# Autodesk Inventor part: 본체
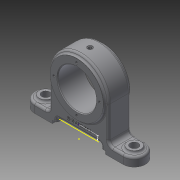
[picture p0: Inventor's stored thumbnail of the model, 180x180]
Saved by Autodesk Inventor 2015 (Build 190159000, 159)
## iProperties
Created: 2019-05
Part Number: 본체
Material: 일반
Document SubType Name: Modeling
Designer: 102101
Density: 1 g/cm^3
Appearance: 기본값
Author: 102101
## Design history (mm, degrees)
sketch "스케치1"
  geometry: L1 (75, -15)-(-75, -15); L2 (-75, -15)-(-75, 15); L3 (-75, 15)-(75, 15); L4 (75, 15)-(75, -15); L5 (75, -15)-(-75, 15); L6 (-75, -15)-(75, 15); 1 further point
  constraints: 12 end point, 2 midpoint, 2 parallel, 1 horizontal, 1 perpendicular
  dimensions: "d0" = 150 distance of L2.end L3.end; "d1" = 30 distance of L3.end L1.start
extrude "돌출1" new body sketch "스케치1" distance "d2" = 12; taper "d3" = 0 deg
fillet "모깎기1" dims "d4" = 15
fillet "모깎기2" dims "d5" = 15
sketch "스케치2"
  geometry: C1 r 9 at (-60, 0); C2 r 9 at (60, 0); 1 further point
  constraints: 2 centre point, 2 horizontal alignment
  dimensions: "d6" = 18 diameter of C1; "d7" = 18 diameter of C2; "d8" = 120 distance of C2.centre C1.centre; "d9" = 60 distance of point (0, 0) C1.centre
extrude "돌출2" join sketch "스케치2" distance "d10" = 3; taper "d11" = 0 deg
sketch "스케치3"
  geometry: L1 (0, 0)-(-120, 0) reference; L2 (-96, 0)-(-24, 0); L3 (-24, 0)-(-24, 4); L4 (-24, 4)-(-96, 4); L5 (-96, 4)-(-96, 0); 2 further points
  constraints: 8 end point, 2 midpoint, 2 parallel, 1 horizontal, 1 perpendicular, 1 point on line
  dimensions: "d12" = 72 distance of L3.end L4.end; "d13" = 4 distance between parallel lines of L4 L1
extrude "돌출3" cut sketch "스케치3" stored distance "d14" = 3; taper "d15" = 0 deg
sketch "스케치4"
  geometry: L1 (-96, 4)-(-24, 4) reference; L2 (-90, 4)-(-30, 4); L3 (-30, 4)-(-30, 10); L4 (-30, 10)-(-90, 10); L5 (-90, 10)-(-90, 4); 2 further points
  constraints: 8 end point, 2 midpoint, 2 parallel, 1 horizontal, 1 perpendicular, 1 point on line
  dimensions: "d16" = 60 distance between parallel lines of L3 L5; "d17" = 6 distance between parallel lines of L1 L4
extrude "돌출4" cut sketch "스케치4" stored distance "d18" = 3; taper "d19" = 0 deg
sketch "스케치5"
  geometry: L1 (40, -15)-(-40, -15); L2 (-40, -15)-(-40, 15); L3 (-40, 15)-(40, 15); L4 (40, 15)-(40, -15); L5 (40, -15)-(-40, 15); L6 (-40, -15)-(40, 15); 1 further point
  constraints: 12 end point, 2 midpoint, 2 parallel, 1 horizontal, 1 perpendicular
  dimensions: "d20" = 80 distance of L2.end L3.end; "d21" = 30 distance between parallel lines of L1 L3
extrude "돌출5" join sketch "스케치5" distance "d22" = 48; taper "d23" = 0 deg
sketch "스케치6"
  geometry: L1 (40, 60)-(-40, 60) reference; L2 (-36, 4)-(-36, 0) reference; L3 (-36, 0)-(-75, 0) reference; L4 (-75, 0)-(-75, 12) reference; L5 (-75, 12)-(-69, 12) reference; L6 (-69, 12)-(-69, 15) reference; L7 (-69, 15)-(-51, 15) reference; L8 (-51, 15)-(-51, 12) reference; L9 (-51, 12)-(-40, 12) reference; L10 (-40, 12)-(-40, 60) reference; L11 (-40, 60)-(40, 60) reference; L12 (40, 60)-(40, 12) reference; L13 (40, 12)-(51, 12) reference; L14 (51, 12)-(51, 15) reference; L15 (51, 15)-(69, 15) reference; L16 (69, 15)-(69, 12) reference; L17 (69, 12)-(75, 12) reference; L18 (75, 12)-(75, 0) reference; L19 (75, 0)-(36, 0) reference; L20 (36, 0)-(36, 4) reference; L21 (36, 4)-(30, 4) reference; L22 (30, 4)-(30, 10) reference; L23 (30, 10)-(-30, 10) reference; L24 (-30, 10)-(-30, 4) reference; L25 (-30, 4)-(-36, 4) reference; C1 r 40 at (0, 60); 3 further points
  constraints: 3 vertical alignment, 2 midpoint, 1 centre point
  dimensions: "d24" = 80 diameter of C1; "d25" = 60 distance of point (0, 0) C1.centre
extrude "돌출6" join sketch "스케치6" stored distance "d26" = 30; taper "d27" = 0 deg
sketch "스케치7"
  geometry: L1 (-36, 4)-(-36, 0) reference; L2 (-36, 0)-(-75, 0) reference; L3 (-75, 0)-(-75, 12) reference; L4 (-75, 12)-(-69, 12) reference; L5 (-69, 12)-(-69, 15) reference; L6 (-69, 15)-(-51, 15) reference; L7 (-51, 15)-(-51, 12) reference; L8 (-51, 12)-(-40, 12) reference; L9 (-40, 12)-(-40, 60) reference; L10 (40, 60)-(40, 12) reference; L11 (40, 12)-(51, 12) reference; L12 (51, 12)-(51, 15) reference; L13 (51, 15)-(69, 15) reference; L14 (69, 15)-(69, 12) reference; L15 (69, 12)-(75, 12) reference; L16 (75, 12)-(75, 0) reference; L17 (75, 0)-(36, 0) reference; L18 (36, 0)-(36, 4) reference; L19 (36, 4)-(30, 4) reference; L20 (30, 4)-(30, 10) reference; L21 (30, 10)-(-30, 10) reference; L22 (-30, 10)-(-30, 4) reference; L23 (-30, 4)-(-36, 4) reference; C1 r 36 at (0, 60); A1 r 40 centre (0, 60) between (40, 60) and (-40, 60) reference; 1 further point
  constraints: 1 centre point, 1 coincident
  dimensions: "d28" = 72 diameter of C1
extrude "돌출7" join sketch "스케치7" stored distance "d29" = 36; taper "d30" = 0 deg
sketch "스케치8"
  geometry: C1 r 26 at (0, 0); 1 further point
  constraints: 1 centre point, 1 vertical alignment
  dimensions: "d31" = 52 diameter of C1; "d32" = 60 distance of point (0, -60) C1.centre
extrude "돌출8" cut sketch "스케치8" stored distance "d33" = 10; taper "d34" = 0 deg
sketch "스케치9"
  geometry: 2 further points
  dimensions: "d35" = 91 distance of point (0, -60) point (0, 31)
hole "구멍1" sketch "스케치9" at (0, 31) diameter "d36" = 3.242; stored, may be unused: countersink angle "d40" = 90 deg, drill point angle "d42" = 118 deg; dims "d37" = 6, "d38" = 4, "d39" = 2, "d41" = 8
sketch "스케치10"
  geometry: A1 r 15 centre (0, 0) between (0, 15) and (0, -15) reference; 1 further point
hole "구멍2" sketch "스케치10" at (0, 0) diameter "d46" = 11; stored, may be unused: countersink angle "d50" = 90 deg, drill point angle "d52" = 118 deg; dims "d47" = 6, "d48" = 4, "d49" = 2, "d51" = 8
node "작업 평면1"
sketch "스케치11"
  geometry: 1 further point
hole "구멍3" sketch "스케치11" at (0, 0) diameter "d54" = 4.917; stored, may be unused: countersink angle "d58" = 90 deg, drill point angle "d60" = 118 deg; dims "d55" = 8, "d56" = 7, "d57" = 1, "d59" = 10
sketch "스케치12"
  geometry: 1 further point
hole "구멍4" sketch "스케치12" at (0, 0) diameter "d61" = 2; stored, may be unused: countersink angle "d65" = 90 deg, drill point angle "d67" = 118 deg; dims "d62" = 8, "d63" = 7, "d64" = 1, "d66" = 30
fillet "모깎기3" dims "d68" = 3
chamfer "모따기1" distance "d69" = 1; stored, may be unused: second distance "d70" = 2, angle "d71" = 45 deg
sketch "스케치13"
  geometry: C1 r 1.5 at (0, 26); 2 further points
  constraints: 2 vertical alignment, 1 centre point, 1 other
  dimensions: "d72" = 3 diameter of C1
extrude "돌출9" cut sketch "스케치13" stored distance "d73" = 10; taper "d74" = 0 deg
fillet "모깎기4" dims "d75" = 6
fillet "모깎기5" dims "d76" = 3
fillet "모깎기6" dims "d77" = 3
fillet "모깎기7" dims "d78" = 3
fillet "모깎기8" dims "d79" = 3
sketch "스케치14"
  geometry: L1 (-63, 10)-(-9, 10) reference; 2 further points
  constraints: 1 vertical alignment, 1 other
  dimensions: "d80" = 7 distance from line of L1 point (-36, 17)
node "솔리드1"
pattern_circular "원형 패턴1" dims angle "d44" = 360 deg
mirror "대칭1"
mirror "대칭2"
node "절단 모서리 투영1"
node "절단 모서리 투영2"
